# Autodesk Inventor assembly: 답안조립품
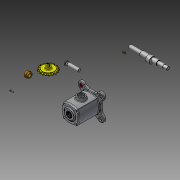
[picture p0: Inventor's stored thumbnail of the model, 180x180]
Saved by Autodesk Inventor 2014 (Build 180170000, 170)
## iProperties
Created: 2016-05
Part Number: 답안조립품
Document SubType Name: Assembly
Designer: Administrator
Author: Administrator
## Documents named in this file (11)
- C:\Users\Administrator\Desktop\460507V1011\답안조립품.iam
- C:\Users\Administrator\Desktop\460507V1011\1-본체.ipt
- C:\Users\Administrator\Desktop\460507V1011\M4x0.7x12.ipt
- C:\Users\Administrator\Desktop\460507V1011\베어링-6203.ipt
- C:\Users\Administrator\Desktop\460507V1011\부시.ipt
- C:\Users\Administrator\Desktop\460507V1011\스프로킷.ipt
- C:\Users\Administrator\Desktop\460507V1011\슬라이더.ipt
- C:\Users\Administrator\Desktop\460507V1011\오일실.ipt
- C:\Users\Administrator\Desktop\460507V1011\커버.ipt
- C:\Users\Administrator\Desktop\460507V1011\키5x5.ipt
- C:\Users\Administrator\Desktop\460507V1011\편심축.ipt
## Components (2 placed, 2 different names)
1. 1-본체:1
2. M4x0.7x12:1
## Named parameters: d2_d0 = 0, d3_d1 = 0
